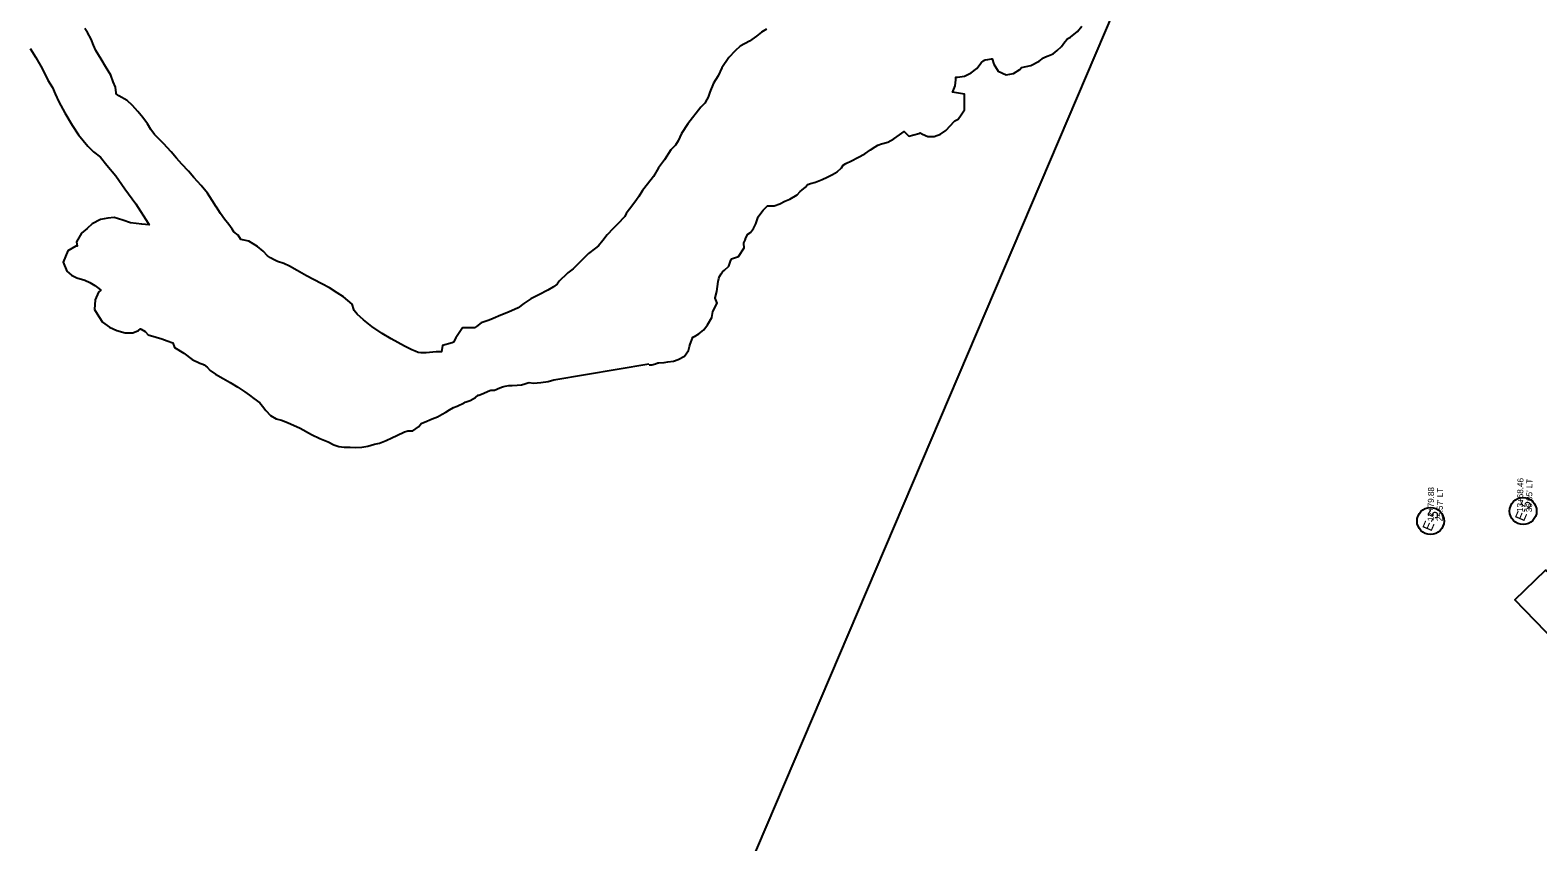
# Model space of a CAD drawing. Extents: x 641687 to 655797, y 406445 to 431088.
# Drawn here: x 651560 to 653056, y 408181 to 408987 of the extents above; entities that cross this region are included whole.
import ezdxf

# ---------------------------------------------------------------- set-up
doc = ezdxf.new("R2010")
doc.units = 0
for name, color, linetype in [('R_Erosion', 7, 'Continuous'), ('R_Erosion_Buffer', 7, 'Continuous'), ('R_No Plot', 7, 'Continuous')]:
    doc.layers.add(name, color=color, linetype=linetype)

msp = doc.modelspace()

# ---------------------------------------------------------------- linework, layer by layer
at = {"layer": 'R_Erosion'}
for centre in [(653041.4, 408509.7), (652949.5, 408499.8)]:
    msp.add_circle(centre, 13.4, dxfattribs=at)
at = {"layer": 'R_Erosion_Buffer'}
for points in [[(652290.4, 408988.1), (652285.6, 408985.1), (652280.4, 408981), (652273.4, 408976.2), (652264.3, 408971.1), (652259.2, 408966.5), (652252.9, 408959.7), (652246.2, 408949.7), (652242.5, 408941.8), (652237.7, 408934.5), (652234.3, 408925.4), (652232.6, 408920.6), (652231.3, 408918.2), (652229.1, 408914.6), (652225.2, 408910.7), (652212.3, 408894.1), (652205.9, 408884.3), (652202.6, 408877.1), (652200.2, 408873), (652195.5, 408868.2), (652189.3, 408858.2), (652183.4, 408850.3), (652178.2, 408841.8), (652172.4, 408834.3), (652167.3, 408827.9), (652163.8, 408821.8), (652161.4, 408818.5), (652157.6, 408813.5), (652151, 408805.1), (652149.8, 408802.2), (652148, 408800.1), (652144.4, 408796.3), (652138.1, 408790.2), (652132.2, 408783.8), (652128, 408778.3), (652123.8, 408773), (652120.8, 408770.6), (652113.7, 408765.4), (652105.2, 408756.7), (652098.7, 408750.2), (652093.4, 408746), (652092.6, 408745.4), (652084.7, 408737.8), (652082.5, 408734.9), (652079.1, 408732.1), (652073.3, 408728.8), (652064.6, 408724.3), (652056.6, 408720.2), (652049.5, 408715.6), (652043.8, 408711.4), (652034.4, 408707.1), (652026.6, 408704), (652019.1, 408700.7), (652015.1, 408699.2), (652007.3, 408696.6), (652002.6, 408692.9), (652000.5, 408691.5), (651988.8, 408691.5), (651982, 408681.7), (651979.9, 408677.3), (651978.3, 408676.8), (651968.7, 408674.1), (651968, 408667.9), (651962.6, 408667.7), (651952.7, 408666.9), (651947.2, 408666.9), (651944.6, 408667.2), (651941.8, 408668.3), (651938.3, 408669.8), (651931.1, 408673.4), (651917.9, 408680.6), (651908.9, 408685.8), (651898.8, 408693), (651890.5, 408699.5), (651884, 408705.2), (651881.2, 408708.8), (651880.7, 408709.8), (651879.2, 408715.2), (651870.7, 408722.5), (651864.2, 408726.4), (651856.6, 408731.2), (651849.1, 408735.1), (651840.7, 408739.7), (651833.9, 408743.2), (651824.5, 408748.6), (651817, 408752.7), (651811.4, 408755.3), (651805.1, 408757.5), (651801, 408759.3), (651798.3, 408760.9), (651795.3, 408763.1), (651790.8, 408767.8), (651785.4, 408772.4), (651776.5, 408777.6), (651770.5, 408779), (651768.8, 408779.3), (651765.9, 408783.5), (651761.9, 408786.9), (651760.2, 408789.4), (651756.7, 408794), (651752.6, 408799.4), (651748.5, 408804.9), (651744.4, 408811.3), (651744.1, 408811.8), (651740.3, 408817.8), (651735.6, 408825.2), (651729.2, 408832.9), (651721.9, 408840.8), (651716.9, 408847.2), (651710.3, 408854), (651704.7, 408860), (651699.5, 408866.3), (651692.1, 408874.6), (651682.9, 408883.4), (651679.3, 408888.5), (651676.2, 408894), (651671.5, 408900.2), (651666.6, 408906.2), (651661.3, 408912.2), (651655.8, 408917.1), (651647.5, 408921.9), (651645.1, 408923.7), (651644.8, 408924.9), (651644.2, 408930.3), (651642, 408935.6), (651639.7, 408942.2), (651634.5, 408950.8), (651630, 408958.3), (651624.9, 408966.7), (651622.4, 408972), (651620.1, 408977.9), (651616.6, 408984.7), (651614, 408988.7)], [(652290.4, 408988.1), (652285.6, 408985.1), (652280.4, 408981), (652273.4, 408976.2), (652264.3, 408971.1), (652259.2, 408966.5), (652252.9, 408959.7), (652246.2, 408949.7), (652242.5, 408941.8), (652237.7, 408934.5), (652234.3, 408925.4), (652232.6, 408920.6), (652231.3, 408918.2), (652229.1, 408914.6), (652225.2, 408910.7), (652212.3, 408894.1), (652205.9, 408884.3), (652202.6, 408877.1), (652200.2, 408873), (652195.5, 408868.2), (652189.3, 408858.2), (652183.4, 408850.3), (652178.2, 408841.8), (652172.4, 408834.3), (652167.3, 408827.9), (652163.8, 408821.8), (652161.4, 408818.5), (652157.6, 408813.5), (652151, 408805.1), (652149.8, 408802.2), (652148, 408800.1), (652144.4, 408796.3), (652138.1, 408790.2), (652132.2, 408783.8), (652128, 408778.3), (652123.8, 408773), (652120.8, 408770.6), (652113.7, 408765.4), (652105.2, 408756.7), (652098.7, 408750.2), (652093.4, 408746), (652092.6, 408745.4), (652084.7, 408737.8), (652082.5, 408734.9), (652079.1, 408732.1), (652073.3, 408728.8), (652064.6, 408724.3), (652056.6, 408720.2), (652049.5, 408715.6), (652043.8, 408711.4), (652034.4, 408707.1), (652026.6, 408704), (652019.1, 408700.7), (652015.1, 408699.2), (652007.3, 408696.6), (652002.6, 408692.9), (652000.5, 408691.5), (651988.8, 408691.5), (651982, 408681.7), (651979.9, 408677.3), (651978.3, 408676.8), (651968.7, 408674.1), (651968, 408667.9), (651962.6, 408667.7), (651952.7, 408666.9), (651947.2, 408666.9), (651944.6, 408667.2), (651941.8, 408668.3), (651938.3, 408669.8), (651931.1, 408673.4), (651917.9, 408680.6), (651908.9, 408685.8), (651898.8, 408693), (651890.5, 408699.5), (651884, 408705.2), (651881.2, 408708.8), (651880.7, 408709.8), (651879.2, 408715.2), (651870.7, 408722.5), (651864.2, 408726.4), (651856.6, 408731.2), (651849.1, 408735.1), (651840.7, 408739.7), (651833.9, 408743.2), (651824.5, 408748.6), (651817, 408752.7), (651811.4, 408755.3), (651805.1, 408757.5), (651801, 408759.3), (651798.3, 408760.9), (651795.3, 408763.1), (651790.8, 408767.8), (651785.4, 408772.4), (651776.5, 408777.6), (651770.5, 408779), (651768.8, 408779.3), (651765.9, 408783.5), (651761.9, 408786.9), (651760.2, 408789.4), (651756.7, 408794), (651752.6, 408799.4), (651748.5, 408804.9), (651744.4, 408811.3), (651744.1, 408811.8), (651740.3, 408817.8), (651735.6, 408825.2), (651729.2, 408832.9), (651721.9, 408840.8), (651716.9, 408847.2), (651710.3, 408854), (651704.7, 408860), (651699.5, 408866.3), (651692.1, 408874.6), (651682.9, 408883.4), (651679.3, 408888.5), (651676.2, 408894), (651671.5, 408900.2), (651666.6, 408906.2), (651661.3, 408912.2), (651655.8, 408917.1), (651647.5, 408921.9), (651645.1, 408923.7), (651644.8, 408924.9), (651644.2, 408930.3), (651642, 408935.6), (651639.7, 408942.2), (651634.5, 408950.8), (651630, 408958.3), (651624.9, 408966.7), (651622.4, 408972), (651620.1, 408977.9), (651616.6, 408984.7), (651614, 408988.7)], [(652290.4, 408988.1), (652285.6, 408985.1), (652280.4, 408981), (652273.4, 408976.2), (652264.3, 408971.1), (652259.2, 408966.5), (652252.9, 408959.7), (652246.2, 408949.7), (652242.5, 408941.8), (652237.7, 408934.5), (652234.3, 408925.4), (652232.6, 408920.6), (652231.3, 408918.2), (652229.1, 408914.6), (652225.2, 408910.7), (652212.3, 408894.1), (652205.9, 408884.3), (652202.6, 408877.1), (652200.2, 408873), (652195.5, 408868.2), (652189.3, 408858.2), (652183.4, 408850.3), (652178.2, 408841.8), (652172.4, 408834.3), (652167.3, 408827.9), (652163.8, 408821.8), (652161.4, 408818.5), (652157.6, 408813.5), (652151, 408805.1), (652149.8, 408802.2), (652148, 408800.1), (652144.4, 408796.3), (652138.1, 408790.2), (652132.2, 408783.8), (652128, 408778.3), (652123.8, 408773), (652120.8, 408770.6), (652113.7, 408765.4), (652105.2, 408756.7), (652098.7, 408750.2), (652093.4, 408746), (652092.6, 408745.4), (652084.7, 408737.8), (652082.5, 408734.9), (652079.1, 408732.1), (652073.3, 408728.8), (652064.6, 408724.3), (652056.6, 408720.2), (652049.5, 408715.6), (652043.8, 408711.4), (652034.4, 408707.1), (652026.6, 408704), (652019.1, 408700.7), (652015.1, 408699.2), (652007.3, 408696.6), (652002.6, 408692.9), (652000.5, 408691.5), (651988.8, 408691.5), (651982, 408681.7), (651979.9, 408677.3), (651978.3, 408676.8), (651968.7, 408674.1), (651968, 408667.9), (651962.6, 408667.7), (651952.7, 408666.9), (651947.2, 408666.9), (651944.6, 408667.2), (651941.8, 408668.3), (651938.3, 408669.8), (651931.1, 408673.4), (651917.9, 408680.6), (651908.9, 408685.8), (651898.8, 408693), (651890.5, 408699.5), (651884, 408705.2), (651881.2, 408708.8), (651880.7, 408709.8), (651879.2, 408715.2), (651870.7, 408722.5), (651864.2, 408726.4), (651856.6, 408731.2), (651849.1, 408735.1), (651840.7, 408739.7), (651833.9, 408743.2), (651824.5, 408748.6), (651817, 408752.7), (651811.4, 408755.3), (651805.1, 408757.5), (651801, 408759.3), (651798.3, 408760.9), (651795.3, 408763.1), (651790.8, 408767.8), (651785.4, 408772.4), (651776.5, 408777.6), (651770.5, 408779), (651768.8, 408779.3), (651765.9, 408783.5), (651761.9, 408786.9), (651760.2, 408789.4), (651756.7, 408794), (651752.6, 408799.4), (651748.5, 408804.9), (651744.4, 408811.3), (651744.1, 408811.8), (651740.3, 408817.8), (651735.6, 408825.2), (651729.2, 408832.9), (651721.9, 408840.8), (651716.9, 408847.2), (651710.3, 408854), (651704.7, 408860), (651699.5, 408866.3), (651692.1, 408874.6), (651682.9, 408883.4), (651679.3, 408888.5), (651676.2, 408894), (651671.5, 408900.2), (651666.6, 408906.2), (651661.3, 408912.2), (651655.8, 408917.1), (651647.5, 408921.9), (651645.1, 408923.7), (651644.8, 408924.9), (651644.2, 408930.3), (651642, 408935.6), (651639.7, 408942.2), (651634.5, 408950.8), (651630, 408958.3), (651624.9, 408966.7), (651622.4, 408972), (651620.1, 408977.9), (651616.6, 408984.7), (651614, 408988.7)], [(652174, 408654.7), (652176.7, 408654.9), (652180.1, 408655.9), (652182.5, 408656.8), (652183.5, 408656.9), (652189, 408657.2), (652192.6, 408657.7), (652198.1, 408658.5), (652202.9, 408660), (652209, 408663.3), (652213, 408669.2), (652214, 408672.9), (652214.8, 408675.4), (652217, 408681.3), (652217, 408682.2), (652219, 408683), (652223.2, 408685.5), (652228.2, 408689.5), (652232, 408694.6), (652236.3, 408701.7), (652237.1, 408707.8), (652241.5, 408716), (652239.5, 408721), (652239.6, 408721.2), (652241.2, 408727.7), (652242.6, 408737.6), (652243.1, 408740.4), (652243.9, 408742.5), (652245.5, 408745.2), (652246.7, 408747.2), (652248.8, 408748.9), (652253.1, 408752.9), (652255, 408758.8), (652255.1, 408758.9), (652255.7, 408759.9), (652262.8, 408762.3), (652268.1, 408771.1), (652267.9, 408775.3), (652268, 408775.9), (652269.1, 408778.5), (652270, 408780.8), (652271.9, 408784.4), (652271.9, 408784.5), (652274.5, 408786.3), (652277.6, 408790.2), (652280, 408794.8), (652281.4, 408799.8), (652282.2, 408801.6), (652283.7, 408804), (652287.1, 408808.5), (652291.4, 408812.8), (652298.1, 408812.8), (652303.7, 408814.6), (652308.5, 408817.2), (652313.6, 408819.3), (652321, 408823.6), (652323.8, 408826.8), (652325.5, 408828.1), (652329.2, 408831.2), (652331.1, 408833.7), (652331.3, 408833.8), (652334.1, 408834.9), (652338.9, 408836.2), (652345.6, 408838.9), (652350.7, 408841.1), (652355.9, 408843.6), (652360.6, 408846.4), (652365, 408850.5), (652366.6, 408853), (652369.3, 408854.6), (652374.7, 408857.4), (652381.1, 408860.5), (652387.9, 408864.4), (652393.8, 408868.1), (652398.2, 408871.1), (652401, 408872.7), (652404.6, 408874.1), (652410.7, 408875.8), (652416.8, 408879.2), (652422.5, 408883), (652427, 408886.5), (652431.8, 408881.7), (652441.7, 408884.5), (652443, 408885.1), (652445.4, 408883.9), (652450.6, 408881.6), (652456.7, 408881.6), (652463.2, 408883.9), (652468.5, 408887.5), (652473.2, 408892.4), (652476.3, 408895.9), (652477.5, 408896.9), (652480.5, 408898.7), (652483.5, 408903), (652486.9, 408907.8), (652486.9, 408923.5), (652475.1, 408925.3), (652475.8, 408926.9), (652477.6, 408931.6), (652478.5, 408937.8), (652478.3, 408940), (652478.4, 408940.4), (652478.4, 408940.5), (652479.9, 408940.5), (652487.1, 408941.4), (652493.6, 408944.5), (652499.1, 408948.9), (652503.6, 408954.6), (652506.3, 408956.9), (652507.3, 408957.4), (652510.2, 408958), (652513.8, 408958.5), (652514.5, 408958.6), (652516.1, 408953.3), (652520.4, 408946.3), (652528.3, 408942.8), (652535.7, 408944.1), (652541.8, 408947.8), (652543.6, 408950), (652552.9, 408952), (652561, 408956.3), (652565.3, 408959.4), (652567.3, 408960.6), (652570, 408961.6), (652574.8, 408963.6), (652578.9, 408966.8), (652583.2, 408970.7), (652586.5, 408975.3), (652588.7, 408978.2), (652588.9, 408978.4), (652592, 408979.9), (652599.2, 408985.6), (652603.4, 408990.8)], [(652174, 408654.7), (652176.7, 408654.9), (652180.1, 408655.9), (652182.5, 408656.8), (652183.5, 408656.9), (652189, 408657.2), (652192.6, 408657.7), (652198.1, 408658.5), (652202.9, 408660), (652209, 408663.3), (652213, 408669.2), (652214, 408672.9), (652214.8, 408675.4), (652217, 408681.3), (652217, 408682.2), (652219, 408683), (652223.2, 408685.5), (652228.2, 408689.5), (652232, 408694.6), (652236.3, 408701.7), (652237.1, 408707.8), (652241.5, 408716), (652239.5, 408721), (652239.6, 408721.2), (652241.2, 408727.7), (652242.6, 408737.6), (652243.1, 408740.4), (652243.9, 408742.5), (652245.5, 408745.2), (652246.7, 408747.2), (652248.8, 408748.9), (652253.1, 408752.9), (652255, 408758.8), (652255.1, 408758.9), (652255.7, 408759.9), (652262.8, 408762.3), (652268.1, 408771.1), (652267.9, 408775.3), (652268, 408775.9), (652269.1, 408778.5), (652270, 408780.8), (652271.9, 408784.4), (652271.9, 408784.5), (652274.5, 408786.3), (652277.6, 408790.2), (652280, 408794.8), (652281.4, 408799.8), (652282.2, 408801.6), (652283.7, 408804), (652287.1, 408808.5), (652291.4, 408812.8), (652298.1, 408812.8), (652303.7, 408814.6), (652308.5, 408817.2), (652313.6, 408819.3), (652321, 408823.6), (652323.8, 408826.8), (652325.5, 408828.1), (652329.2, 408831.2), (652331.1, 408833.7), (652331.3, 408833.8), (652334.1, 408834.9), (652338.9, 408836.2), (652345.6, 408838.9), (652350.7, 408841.1), (652355.9, 408843.6), (652360.6, 408846.4), (652365, 408850.5), (652366.6, 408853), (652369.3, 408854.6), (652374.7, 408857.4), (652381.1, 408860.5), (652387.9, 408864.4), (652393.8, 408868.1), (652398.2, 408871.1), (652401, 408872.7), (652404.6, 408874.1), (652410.7, 408875.8), (652416.8, 408879.2), (652422.5, 408883), (652427, 408886.5), (652431.8, 408881.7), (652441.7, 408884.5), (652443, 408885.1), (652445.4, 408883.9), (652450.6, 408881.6), (652456.7, 408881.6), (652463.2, 408883.9), (652468.5, 408887.5), (652473.2, 408892.4), (652476.3, 408895.9), (652477.5, 408896.9), (652480.5, 408898.7), (652483.5, 408903), (652486.9, 408907.8), (652486.9, 408923.5), (652475.1, 408925.3), (652475.8, 408926.9), (652477.6, 408931.6), (652478.5, 408937.8), (652478.3, 408940), (652478.4, 408940.4), (652478.4, 408940.5), (652479.9, 408940.5), (652487.1, 408941.4), (652493.6, 408944.5), (652499.1, 408948.9), (652503.6, 408954.6), (652506.3, 408956.9), (652507.3, 408957.4), (652510.2, 408958), (652513.8, 408958.5), (652514.5, 408958.6), (652516.1, 408953.3), (652520.4, 408946.3), (652528.3, 408942.8), (652535.7, 408944.1), (652541.8, 408947.8), (652543.6, 408950), (652552.9, 408952), (652561, 408956.3), (652565.3, 408959.4), (652567.3, 408960.6), (652570, 408961.6), (652574.8, 408963.6), (652578.9, 408966.8), (652583.2, 408970.7), (652586.5, 408975.3), (652588.7, 408978.2), (652588.9, 408978.4), (652592, 408979.9), (652599.2, 408985.6), (652603.4, 408990.8)], [(651559.6, 408968.7), (651565.3, 408959.9), (651571.4, 408948.8), (651577.1, 408937.5), (651581.8, 408930), (651584.5, 408923.8), (651587.9, 408916), (651593.9, 408905), (651601.3, 408892.6), (651607.5, 408883.1), (651616.7, 408871.9), (651622.6, 408866.4), (651629.3, 408861), (651635.8, 408853.1), (651644.6, 408842.3), (651653.4, 408829.6), (651664.6, 408814.7), (651676.6, 408795.4), (651677.7, 408793.7), (651670.3, 408794.5), (651659.2, 408795.9), (651651.7, 408798.3), (651642.9, 408801), (651636.8, 408800.3), (651629.4, 408799.2), (651621.2, 408794.8), (651616.2, 408790.3), (651610.5, 408785.6), (651605.6, 408776.9), (651606.2, 408772.6), (651604.8, 408772.5), (651596.9, 408768.1), (651592.4, 408756.9), (651596, 408747.8), (651600.6, 408744), (651606, 408741.1), (651614, 408738.8), (651618.7, 408736.6), (651623.9, 408733.6), (651627.9, 408730.6), (651629.9, 408728.8), (651627.3, 408726.9), (651624.1, 408719.3), (651623.6, 408709.8), (651627.6, 408702.7), (651631.4, 408697.3), (651638.2, 408692.4), (651645.6, 408689), (651654, 408686.6), (651661.4, 408686.6), (651667.2, 408688.8), (651669.2, 408690.6), (651669.7, 408690.2), (651673.8, 408687.9), (651676.8, 408684.7), (651684.8, 408682.4), (651690.4, 408680.7), (651695.5, 408678.8), (651701.3, 408676.6), (651703, 408671.9), (651712, 408666.3), (651720.5, 408660.3), (651727.9, 408656.5), (651731.1, 408655.6), (651732.2, 408655), (651735.2, 408652.4), (651738.3, 408649.3), (651743.7, 408645.5), (651751.3, 408641.4), (651758, 408637.4), (651765.7, 408632.8), (651772.6, 408628.2), (651777.4, 408624.8), (651781.6, 408621.6), (651787.5, 408617.3), (651790.2, 408613.9), (651793.4, 408609.4), (651798.1, 408604.5), (651803.9, 408601.4), (651809, 408600.1), (651815, 408597.7), (651827.7, 408592), (651838.9, 408585.7), (651847.1, 408581.9), (651855.3, 408578.3), (651861, 408575.4), (651866.1, 408573.9), (651871.4, 408573.3), (651877.1, 408573.1), (651882.2, 408572.8), (651888.7, 408573), (651894.7, 408574.3), (651901.3, 408576.2), (651906.3, 408577.1), (651913.1, 408579.8), (651918.5, 408582.4), (651923.4, 408584.6), (651931, 408588.3), (651933.5, 408589.1), (651934.3, 408589.3), (651934.7, 408589.3), (651939.5, 408589.3), (651945, 408593.3), (651947.1, 408595.6), (651947.8, 408596.5), (651948.3, 408596.8), (651950.9, 408597.8), (651958.7, 408601.2), (651963.9, 408603.3), (651968.5, 408605.9), (651972.3, 408608), (651975.9, 408610.3), (651979.7, 408612.5), (651983.3, 408613.8), (651990.4, 408617.3), (651991.3, 408617.9), (651996.3, 408619.3), (652001.6, 408622.4), (652004.3, 408624.7), (652004.9, 408624.9), (652009.3, 408626.3), (652014.3, 408628.6), (652016.8, 408629.7), (652020.4, 408629.8), (652025.9, 408631.9), (652028.3, 408632.9), (652031.2, 408633.7), (652034.6, 408634.3), (652038, 408634.5), (652042.8, 408634.6), (652047.3, 408635.1), (652050.7, 408636), (652053.5, 408637.1), (652053.7, 408637.1), (652054.9, 408637.2), (652059.1, 408636.8), (652066.6, 408637.2), (652073.7, 408638.4), (652079.5, 408640), (652173.8, 408656)], [(651559.6, 408968.7), (651565.3, 408959.9), (651571.4, 408948.8), (651577.1, 408937.5), (651581.8, 408930), (651584.5, 408923.8), (651587.9, 408916), (651593.9, 408905), (651601.3, 408892.6), (651607.5, 408883.1), (651616.7, 408871.9), (651622.6, 408866.4), (651629.3, 408861), (651635.8, 408853.1), (651644.6, 408842.3), (651653.4, 408829.6), (651664.6, 408814.7), (651676.6, 408795.4), (651677.7, 408793.7), (651670.3, 408794.5), (651659.2, 408795.9), (651651.7, 408798.3), (651642.9, 408801), (651636.8, 408800.3), (651629.4, 408799.2), (651621.2, 408794.8), (651616.2, 408790.3), (651610.5, 408785.6), (651605.6, 408776.9), (651606.2, 408772.6), (651604.8, 408772.5), (651596.9, 408768.1), (651592.4, 408756.9), (651596, 408747.8), (651600.6, 408744), (651606, 408741.1), (651614, 408738.8), (651618.7, 408736.6), (651623.9, 408733.6), (651627.9, 408730.6), (651629.9, 408728.8), (651627.3, 408726.9), (651624.1, 408719.3), (651623.6, 408709.8), (651627.6, 408702.7), (651631.4, 408697.3), (651638.2, 408692.4), (651645.6, 408689), (651654, 408686.6), (651661.4, 408686.6), (651667.2, 408688.8), (651669.2, 408690.6), (651669.7, 408690.2), (651673.8, 408687.9), (651676.8, 408684.7), (651684.8, 408682.4), (651690.4, 408680.7), (651695.5, 408678.8), (651701.3, 408676.6), (651703, 408671.9), (651712, 408666.3), (651720.5, 408660.3), (651727.9, 408656.5), (651731.1, 408655.6), (651732.2, 408655), (651735.2, 408652.4), (651738.3, 408649.3), (651743.7, 408645.5), (651751.3, 408641.4), (651758, 408637.4), (651765.7, 408632.8), (651772.6, 408628.2), (651777.4, 408624.8), (651781.6, 408621.6), (651787.5, 408617.3), (651790.2, 408613.9), (651793.4, 408609.4), (651798.1, 408604.5), (651803.9, 408601.4), (651809, 408600.1), (651815, 408597.7), (651827.7, 408592), (651838.9, 408585.7), (651847.1, 408581.9), (651855.3, 408578.3), (651861, 408575.4), (651866.1, 408573.9), (651871.4, 408573.3), (651877.1, 408573.1), (651882.2, 408572.8), (651888.7, 408573), (651894.7, 408574.3), (651901.3, 408576.2), (651906.3, 408577.1), (651913.1, 408579.8), (651918.5, 408582.4), (651923.4, 408584.6), (651931, 408588.3), (651933.5, 408589.1), (651934.3, 408589.3), (651934.7, 408589.3), (651939.5, 408589.3), (651945, 408593.3), (651947.1, 408595.6), (651947.8, 408596.5), (651948.3, 408596.8), (651950.9, 408597.8), (651958.7, 408601.2), (651963.9, 408603.3), (651968.5, 408605.9), (651972.3, 408608), (651975.9, 408610.3), (651979.7, 408612.5), (651983.3, 408613.8), (651990.4, 408617.3), (651991.3, 408617.9), (651996.3, 408619.3), (652001.6, 408622.4), (652004.3, 408624.7), (652004.9, 408624.9), (652009.3, 408626.3), (652014.3, 408628.6), (652016.8, 408629.7), (652020.4, 408629.8), (652025.9, 408631.9), (652028.3, 408632.9), (652031.2, 408633.7), (652034.6, 408634.3), (652038, 408634.5), (652042.8, 408634.6), (652047.3, 408635.1), (652050.7, 408636), (652053.5, 408637.1), (652053.7, 408637.1), (652054.9, 408637.2), (652059.1, 408636.8), (652066.6, 408637.2), (652073.7, 408638.4), (652079.5, 408640), (652173.8, 408656)]]:
    msp.add_lwpolyline(points, dxfattribs=at)
at = {"layer": 'R_No Plot'}
for points in [[(654711.2, 408712), (652798.2, 409388.9), (652798.2, 409388.9), (651881.9, 407239.3), (653744.9, 406445.2)], [(653788.4, 408405), (653802.7, 408346.5), (653704.6, 408324), (653285.1, 408338.8), (653257.3, 408294.2), (653165.1, 408285.2), (653033.1, 408421.5), (653063.6, 408451.2), (653099.5, 408427.8), (653336, 408405.1), (653341.6, 408365.4), (653421.2, 408360.7), (653445.5, 408387.5), (653706.1, 408390.8)]]:
    msp.add_lwpolyline(points, close=True, dxfattribs=at)

# ---------------------------------------------------------------- texts
at = {"layer": 'R_Erosion'}
for p in [(653042.1, 408498.8), (652950.2, 408488.9)]:
    msp.add_text('E-5', height=10, rotation=66.9125, dxfattribs=at).set_placement(p)
at = {"layer": 'R_No Plot'}
for s, p in [('13+68.46 ', (653041.2, 408508.8)), ("36.05' LT  ", (653050.2, 408508.6)), ('12+79.88 ', (652952.5, 408499.8)), ("25.57' LT  ", (652961.5, 408499.6))]:
    msp.add_text(s, height=6, rotation=89.0197, dxfattribs=at).set_placement(p)

doc.saveas('drawing.dxf')
